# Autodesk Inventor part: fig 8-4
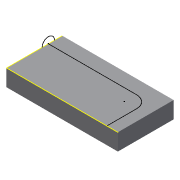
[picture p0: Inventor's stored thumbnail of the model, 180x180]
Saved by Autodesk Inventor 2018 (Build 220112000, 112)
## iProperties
Created: 2009-04
Part Number: fig 8-4
Document SubType Name: Modeling
Designer: Sham
Density: 1 g/cm^3
Material: Generic
Appearance: Default
Author: Sham
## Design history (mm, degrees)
sketch "Sketch1"
  geometry: L1 (-20, 20)-(20, 20); L2 (20, 20)-(20, 0); L3 (20, 0)-(-20, 0); L4 (-20, 0)-(-20, 20)
  constraints: 8 end point
extrude "Extrusion1" new body sketch "Sketch1" distance "d0" = 6; taper "d1" = 0 deg
sketch "Sketch4"
  geometry: L1 (6, 0)-(6, 20) reference; C1 r 2.236 at (6, 15)
  constraints: 1 centre point, 1 point on line
sketch "Sketch5"
  geometry: L1 (-20, 0)-(-20, 20) reference; L2 (20, 0)-(-20, 0) reference; L3 (-20, 15)-(11.667, 15); L4 (16, 10.667)-(16, 0); A1 r 4.333 centre (11.667, 10.667) between (16, 10.667) and (11.667, 15)
  constraints: 4 end point, 2 point on circle, 2 point on line, 1 centre point, 1 tangent
body "Solid1"
